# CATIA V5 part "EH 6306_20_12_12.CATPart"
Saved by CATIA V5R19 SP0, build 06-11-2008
Definition: EH 6306_20_12_12
Nomenclature: EH 6306_20_12_12
Description: PART--DESC
Material "Steel": density 7860 kg/m3, Young's modulus 2e+11 Pa, Poisson ratio 0.266, thermal expansion 1.17e-05 1/K
Bounding box of the stored display mesh (mm): x -11 to 11, y 99.5 to 155.39, z 56.01 to 77.99
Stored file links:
  G:\UTB\Kombinované\Bakalářská práce\Catia\FORMA\EH 6306_20_12_12.CATPart
  D:\Aplikace\CATIA\Nová složka\win_b64\startup\materials\Catalog.CATMaterial
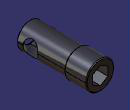
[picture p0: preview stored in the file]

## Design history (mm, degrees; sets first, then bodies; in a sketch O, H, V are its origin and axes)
Body1 "EH 6306_20_12_12" (main body)
  Solid1: solid without history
